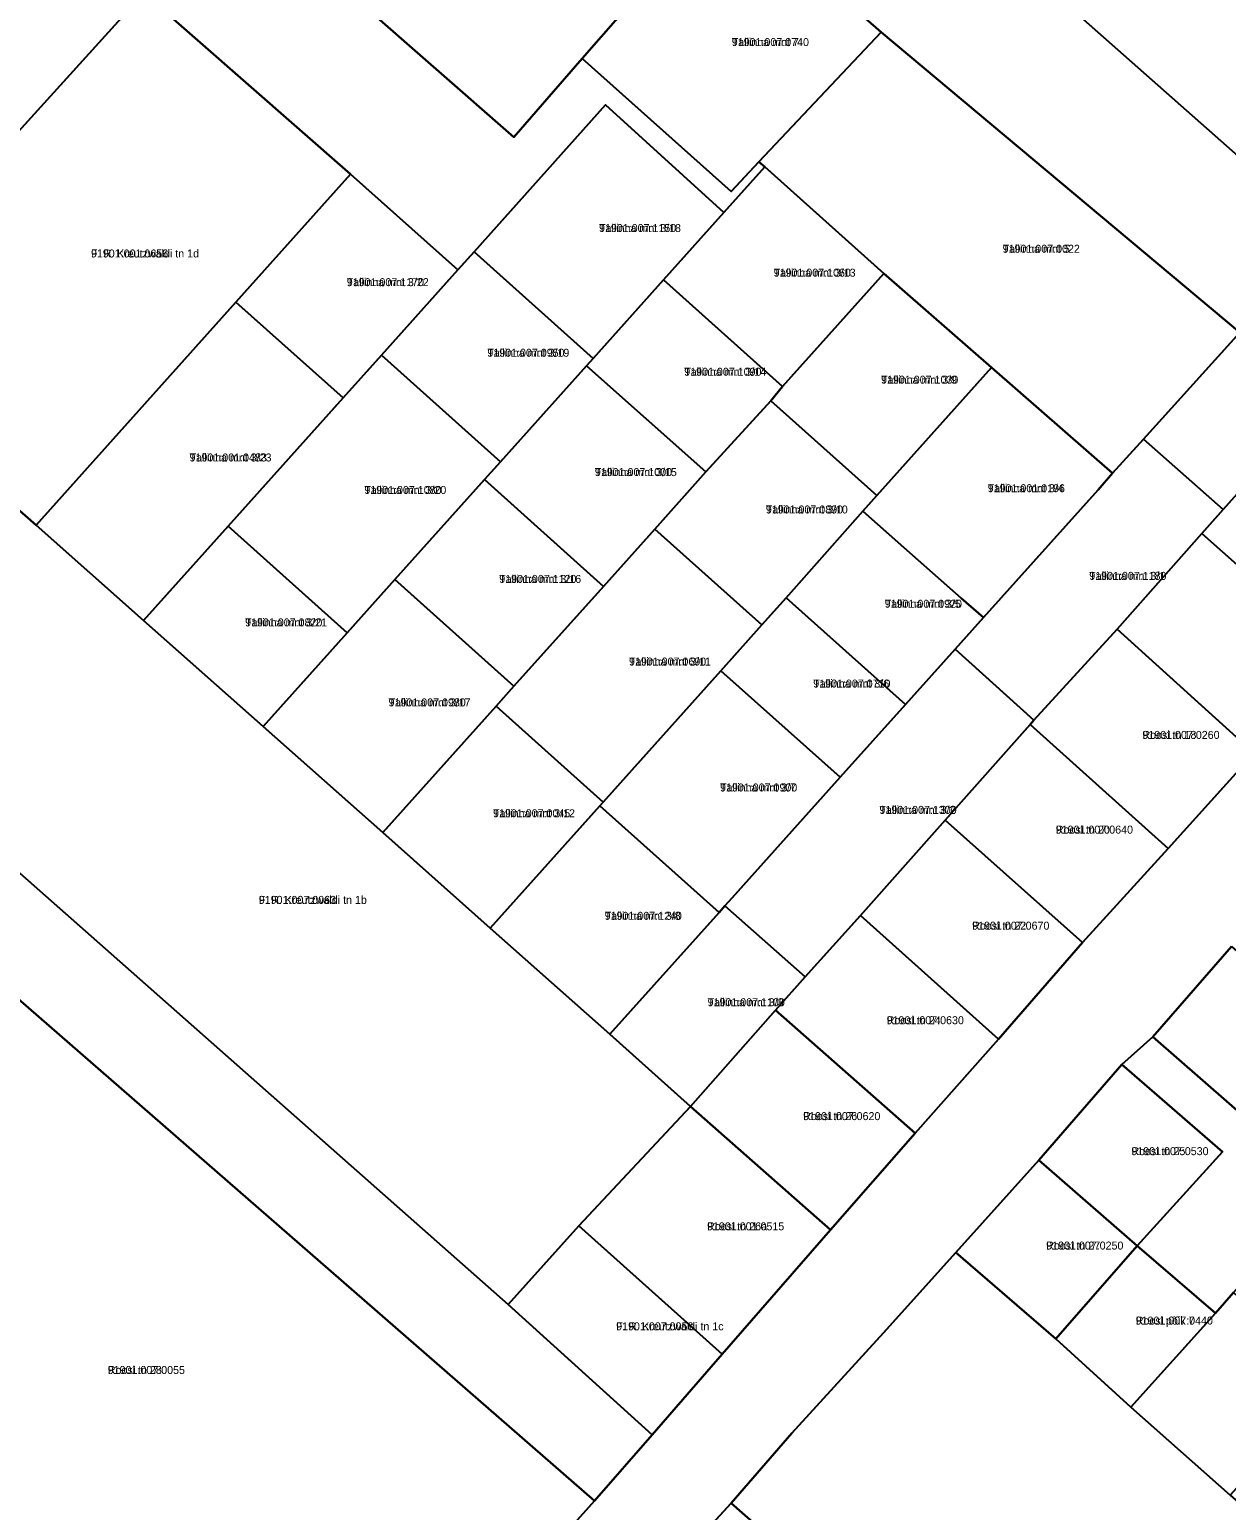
# Model space of a CAD drawing. Extents: x 675810 to 681273, y 6411190 to 6417565.
# Drawn here: x 677289.2 to 677513.9, y 6415777.9 to 6416055.9 of the extents above; entities that cross this region are included whole.
import ezdxf

# ---------------------------------------------------------------- set-up
doc = ezdxf.new("R2010")
doc.units = 0
for name, color, linetype in [('L_AADRESS', 7, 'Continuous'), ('PIIR', 7, 'Continuous'), ('TUNNUS', 7, 'Continuous')]:
    doc.layers.add(name, color=color, linetype=linetype)

msp = doc.modelspace()

# ---------------------------------------------------------------- linework, layer by layer
at = {"layer": 'PIIR'}
for points in [[(677569.88, 6415984.72), (677567.46, 6415999.42), (677560.49, 6416005.51), (677554.29, 6415998.51), (677474.23, 6416069.26), (677521.69, 6416124.52), (677593.8, 6416130.93), (677603.27, 6416122.92), (677623.31, 6416106.01), (677655.68, 6416078.76), (677573.02, 6415981.95)], [(677292.83, 6416112.36), (677321.89, 6416086.81), (677350.97, 6416061.27), (677380.15, 6416035.75), (677392.98, 6416050.46), (677420.91, 6416025.53), (677426.13, 6416031.12), (677427.25, 6416030.13), (677419.57, 6416021.57), (677397.36, 6416041.78), (677372.67, 6416014.22), (677369.61, 6416010.81), (677349.47, 6416028.77), (677310.65, 6416062.83), (677274.52, 6416095.02)], [(677419.76, 6416081.08), (677392.98, 6416050.46), (677380.15, 6416035.75), (677350.97, 6416061.27), (677390.56, 6416106.36)], [(677274.52, 6416095.02), (677310.65, 6416062.83), (677251.96, 6415998.12), (677280.75, 6415972), (677246.4, 6415934.24), (677232.06, 6415952.28), (677223.66, 6415971.45), (677218.41, 6415993.5), (677219.42, 6416010.9), (677223.33, 6416027.1), (677230.03, 6416042.86), (677235.39, 6416051.02), (677273.35, 6416093.91)], [(677420.91, 6416025.53), (677392.98, 6416050.46), (677419.76, 6416081.08), (677449.12, 6416055.4), (677426.13, 6416031.12)], [(677280.75, 6415972), (677251.96, 6415998.12), (677310.65, 6416062.83), (677349.47, 6416028.77), (677327.9, 6416004.72), (677290.41, 6415962.9), (677285.81, 6415966.98)], [(677449.12, 6416055.4), (677516.49, 6415999.07), (677498.38, 6415979.04), (677492.58, 6415972.65), (677469.8, 6415992.51), (677449.6, 6416010.12), (677427.25, 6416030.13), (677426.13, 6416031.12)], [(677419.57, 6416021.57), (677408.25, 6416008.94), (677395.03, 6415994.2), (677372.67, 6416014.22), (677397.36, 6416041.78)], [(677349.47, 6416028.77), (677369.61, 6416010.81), (677355.27, 6415994.81), (677348.06, 6415986.76), (677327.9, 6416004.72)], [(677419.57, 6416021.57), (677427.25, 6416030.13), (677449.6, 6416010.12), (677430.59, 6415988.93), (677408.25, 6416008.94)], [(677369.61, 6416010.81), (677372.67, 6416014.22), (677395.03, 6415994.2), (677393.78, 6415992.81), (677377.63, 6415974.79), (677355.27, 6415994.81)], [(677430.59, 6415988.93), (677428.39, 6415986.21), (677416.18, 6415972.91), (677393.78, 6415992.81), (677395.03, 6415994.2), (677408.25, 6416008.94)], [(677448.3, 6415968.44), (677428.39, 6415986.21), (677430.59, 6415988.93), (677449.6, 6416010.12), (677469.8, 6415992.51)], [(677327.9, 6416004.72), (677348.06, 6415986.76), (677326.47, 6415962.69), (677310.6, 6415944.99), (677290.41, 6415962.9)], [(677516.49, 6415999.07), (677531.68, 6415986.37), (677513.35, 6415965.81), (677498.38, 6415979.04)], [(677348.06, 6415986.76), (677355.27, 6415994.81), (677377.63, 6415974.79), (677374.62, 6415971.43), (677357.79, 6415952.68), (677348.83, 6415942.67), (677326.47, 6415962.69)], [(677416.18, 6415972.91), (677406.6, 6415962.16), (677396.95, 6415951.4), (677374.62, 6415971.43), (677377.63, 6415974.79), (677393.78, 6415992.81)], [(677448.3, 6415968.44), (677469.8, 6415992.51), (677492.58, 6415972.65), (677489.84, 6415969.49), (677468.35, 6415945.54), (677464.14, 6415949.19), (677453.38, 6415958.67), (677445.66, 6415965.54)], [(677426.71, 6415944.15), (677406.6, 6415962.16), (677416.18, 6415972.91), (677428.39, 6415986.21), (677448.3, 6415968.44), (677445.66, 6415965.54), (677431.27, 6415949.23)], [(677531.68, 6415986.37), (677557.77, 6415963.23), (677535.38, 6415938.2), (677509.36, 6415961.33), (677513.35, 6415965.81)], [(677513.35, 6415965.81), (677509.36, 6415961.33), (677493.43, 6415943.34), (677477.81, 6415926.3), (677463, 6415939.58), (677468.35, 6415945.54), (677489.84, 6415969.49), (677492.58, 6415972.65), (677498.38, 6415979.04)], [(677396.95, 6415951.4), (677380.13, 6415932.64), (677357.79, 6415952.68), (677374.62, 6415971.43)], [(677251.36, 6415929.29), (677285.81, 6415966.98), (677290.41, 6415962.9), (677310.6, 6415944.99), (677333.06, 6415925.08), (677355.52, 6415905.18), (677375.71, 6415887.26), (677398.17, 6415867.35), (677413.3, 6415853.76), (677392.33, 6415831.36), (677379.05, 6415816.6)], [(677468.35, 6415945.54), (677463, 6415939.58), (677453.68, 6415929.22), (677431.27, 6415949.23), (677445.66, 6415965.54), (677453.38, 6415958.67), (677464.14, 6415949.19)], [(677326.47, 6415962.69), (677348.83, 6415942.67), (677333.06, 6415925.08), (677310.6, 6415944.99)], [(677380.13, 6415932.64), (677396.95, 6415951.4), (677406.6, 6415962.16), (677426.71, 6415944.15), (677419.02, 6415935.57), (677396.92, 6415910.91), (677376.8, 6415928.92)], [(677535.38, 6415938.2), (677519.18, 6415920.11), (677493.43, 6415943.34), (677509.36, 6415961.33)], [(677355.52, 6415905.18), (677333.06, 6415925.08), (677348.83, 6415942.67), (677357.79, 6415952.68), (677380.13, 6415932.64), (677376.8, 6415928.92)], [(677453.68, 6415929.22), (677441.43, 6415915.56), (677419.02, 6415935.57), (677426.71, 6415944.15), (677431.27, 6415949.23)], [(677493.43, 6415943.34), (677519.18, 6415920.11), (677502.98, 6415902.18), (677477.08, 6415925.45), (677477.81, 6415926.3)], [(677419.75, 6415891.4), (677421.13, 6415892.93), (677441.43, 6415915.56), (677453.68, 6415929.22), (677463, 6415939.58), (677477.81, 6415926.3), (677477.08, 6415925.45), (677461.13, 6415907.48), (677445.21, 6415889.63), (677434.85, 6415878.09)], [(677396.92, 6415910.91), (677419.02, 6415935.57), (677441.43, 6415915.56), (677421.13, 6415892.93), (677419.75, 6415891.4), (677418.66, 6415890.18), (677396.27, 6415910.19)], [(677355.52, 6415905.18), (677376.8, 6415928.92), (677396.92, 6415910.91), (677396.27, 6415910.19), (677375.71, 6415887.26)], [(677461.13, 6415907.48), (677477.08, 6415925.45), (677502.98, 6415902.18), (677486.92, 6415884.51)], [(677396.27, 6415910.19), (677418.66, 6415890.18), (677398.17, 6415867.35), (677375.71, 6415887.26)], [(677445.21, 6415889.63), (677461.13, 6415907.48), (677486.92, 6415884.51), (677471.15, 6415866.41)], [(677212.04, 6415827.9), (677269.04, 6415889.58), (677395.25, 6415779.7), (677339.56, 6415717.51), (677277.14, 6415770.95), (677225.12, 6415816.44)], [(677398.17, 6415867.35), (677418.66, 6415890.18), (677419.75, 6415891.4), (677434.85, 6415878.09), (677429.29, 6415871.81), (677413.3, 6415853.76)], [(677429.29, 6415871.81), (677434.85, 6415878.09), (677445.21, 6415889.63), (677471.15, 6415866.41), (677455.47, 6415848.77)], [(677514.87, 6415883.77), (677533.69, 6415867.35), (677518.93, 6415850.43), (677500.12, 6415866.85)], [(677494.32, 6415861.63), (677500.12, 6415866.85), (677518.93, 6415850.43), (677533.69, 6415867.35), (677538.23, 6415872.55), (677547.73, 6415863.77), (677558.13, 6415875.64), (677562.71, 6415871.54), (677558.63, 6415867.71), (677543.88, 6415850.48), (677528.56, 6415833.83), (677515.27, 6415818.84), (677511.92, 6415814.99), (677497.18, 6415827.61), (677513.18, 6415845.25)], [(677455.47, 6415848.77), (677439.61, 6415830.59), (677413.3, 6415853.76), (677429.29, 6415871.81)], [(677478.72, 6415843.65), (677494.32, 6415861.63), (677513.18, 6415845.25), (677497.18, 6415827.61)], [(677413.3, 6415853.76), (677439.61, 6415830.59), (677419.27, 6415807.26), (677392.33, 6415831.36)], [(677497.18, 6415827.61), (677481.9, 6415810.15), (677463.15, 6415826.36), (677478.72, 6415843.65)], [(677392.33, 6415831.36), (677419.27, 6415807.26), (677406.09, 6415792.13), (677379.05, 6415816.6)], [(677444.1, 6415758.98), (677420.94, 6415779.32), (677432.33, 6415792.43), (677449.54, 6415811.25), (677463.15, 6415826.36), (677481.9, 6415810.15), (677495.98, 6415797.3), (677514.66, 6415780.78), (677536.7, 6415761.6), (677523.83, 6415746.25), (677495.67, 6415713.67), (677477.14, 6415729.95)], [(677495.98, 6415797.3), (677481.9, 6415810.15), (677497.18, 6415827.61), (677511.92, 6415814.99)], [(677495.98, 6415797.3), (677511.92, 6415814.99), (677515.27, 6415818.84), (677533.83, 6415802.03), (677514.66, 6415780.78)]]:
    msp.add_lwpolyline(points, close=True, dxfattribs=at)
for points in [[(677474.23, 6416069.26), (677554.29, 6415998.51), (677569.88, 6415984.72), (677573.02, 6415981.95), (677585.47, 6415963.92), (677586.12, 6415962.99), (677575.06, 6415951.09), (677557.77, 6415963.23), (677531.68, 6415986.37), (677516.49, 6415999.07), (677449.12, 6416055.4), (677419.76, 6416081.08)], [(677251.36, 6415929.29), (677379.05, 6415816.6), (677406.09, 6415792.13), (677395.25, 6415779.7), (677269.04, 6415889.58)], [(677339.56, 6415717.51), (677395.25, 6415779.7), (677406.09, 6415792.13), (677419.27, 6415807.26), (677439.61, 6415830.59), (677455.47, 6415848.77), (677471.15, 6415866.41), (677486.92, 6415884.51), (677502.98, 6415902.18), (677519.18, 6415920.11)], [(677514.87, 6415883.77), (677500.12, 6415866.85), (677494.32, 6415861.63), (677478.72, 6415843.65), (677463.15, 6415826.36), (677449.54, 6415811.25), (677432.33, 6415792.43), (677420.94, 6415779.32), (677408.85, 6415766.14)], [(677408.85, 6415766.14), (677420.94, 6415779.32), (677444.1, 6415758.98)]]:
    msp.add_lwpolyline(points, dxfattribs=at)

# ---------------------------------------------------------------- texts
at = {"layer": 'L_AADRESS'}
for s, p in [('Tallinna mnt 7', (677421.05, 6416052.82)), ('Tallinna mnt 3/18', (677396.12, 6416017.91)), ('F. R. Kreutzwaldi tn 1d', (677300.71, 6416013.14)), ('Tallinna mnt 5', (677471.92, 6416014.02)), ('Tallinna mnt 3/22', (677348.75, 6416007.75)), ('Tallinna mnt 3/13', (677428.92, 6416009.53)), ('Tallinna mnt 3/19', (677375.15, 6415994.5)), ('Tallinna mnt 3/14', (677412.13, 6415990.93)), ('Tallinna mnt 3/9', (677449.09, 6415989.44)), ('Tallinna mnt 3/23', (677319.23, 6415974.84)), ('Tallinna mnt 3/15', (677395.34, 6415972.1)), ('Tallinna mnt 3/20', (677352.05, 6415968.74)), ('Tallinna mnt 3/4', (677469.12, 6415969.07)), ('Tallinna mnt 3/10', (677427.45, 6415965.08)), ('Tallinna mnt 3/16', (677377.38, 6415952.04)), ('Tallinna mnt 3/1', (677488.18, 6415952.62)), ('Tallinna mnt 3/5', (677449.78, 6415947.38)), ('Tallinna mnt 3/21', (677329.66, 6415943.88)), ('Tallinna mnt 3/11', (677401.75, 6415936.53)), ('Tallinna mnt 3/6', (677436.35, 6415932.4)), ('Tallinna mnt 3/17', (677356.6, 6415928.86)), ('Roosi tn 18', (677498.16, 6415922.76)), ('Tallinna mnt 3/7', (677418.85, 6415912.89)), ('Tallinna mnt 3/12', (677376.22, 6415908.05)), ('Tallinna mnt 3/2', (677448.78, 6415908.69)), ('Roosi tn 20', (677481.9, 6415904.98)), ('F. R. Kreutzwaldi tn 1b', (677332.23, 6415891.79)), ('Tallinna mnt 3/8', (677397.18, 6415888.8)), ('Roosi tn 22', (677466.2, 6415886.95)), ('Tallinna mnt 3/3', (677416.51, 6415872.58)), ('Roosi tn 24', (677450.14, 6415869.2)), ('Roosi tn 26', (677434.46, 6415851.2)), ('Roosi tn 25', (677496.09, 6415844.62)), ('Roosi tn 26a', (677416.41, 6415830.51)), ('Roosi tn 27', (677480.1, 6415826.9)), ('Roosi põik 7', (677496.91, 6415812.82)), ('F. R. Kreutzwaldi tn 1c', (677399.34, 6415811.74)), ('Roosi tn 28', (677303.86, 6415803.54))]:
    msp.add_text(s, height=1.5, dxfattribs=at).set_placement(p)
at = {"layer": 'TUNNUS'}
for s, p in [('91901:007:0740', (677421.05, 6416052.82)), ('91901:007:1150', (677396.12, 6416017.91)), ('91901:001:0656', (677300.71, 6416013.14)), ('91901:007:0022', (677471.92, 6416014.02)), ('91901:007:1170', (677348.75, 6416007.75)), ('91901:007:1060', (677428.92, 6416009.53)), ('91901:007:0950', (677375.15, 6415994.5)), ('91901:007:1090', (677412.13, 6415990.93)), ('91901:007:1030', (677449.09, 6415989.44)), ('91901:001:0483', (677319.23, 6415974.84)), ('91901:007:1000', (677395.34, 6415972.1)), ('91901:007:1080', (677352.05, 6415968.74)), ('91901:001:0196', (677469.12, 6415969.07)), ('91901:007:0890', (677427.45, 6415965.08)), ('91901:007:1120', (677377.38, 6415952.04)), ('91901:007:1180', (677488.18, 6415952.62)), ('91901:007:0920', (677449.78, 6415947.38)), ('91901:007:0820', (677329.66, 6415943.88)), ('91901:007:0690', (677401.75, 6415936.53)), ('91901:007:0710', (677436.35, 6415932.4)), ('91901:007:0980', (677356.6, 6415928.86)), ('91901:007:0260', (677498.16, 6415922.76)), ('91901:007:0900', (677418.85, 6415912.89)), ('91901:007:0045', (677376.22, 6415908.05)), ('91901:007:1300', (677448.78, 6415908.69)), ('91901:007:0640', (677481.9, 6415904.98)), ('91901:007:0063', (677332.23, 6415891.79)), ('91901:007:1240', (677397.18, 6415888.8)), ('91901:007:0670', (677466.2, 6415886.95)), ('91901:007:1100', (677416.51, 6415872.58)), ('91901:007:0630', (677450.14, 6415869.2)), ('91901:007:0620', (677434.46, 6415851.2)), ('91901:007:0530', (677496.09, 6415844.62)), ('91901:001:0515', (677416.41, 6415830.51)), ('91901:007:0250', (677480.1, 6415826.9)), ('91901:007:0440', (677496.91, 6415812.82)), ('91901:007:0056', (677399.34, 6415811.74)), ('91901:007:0055', (677303.86, 6415803.54))]:
    msp.add_text(s, height=1.5, dxfattribs=at).set_placement(p)

doc.saveas('drawing.dxf')
